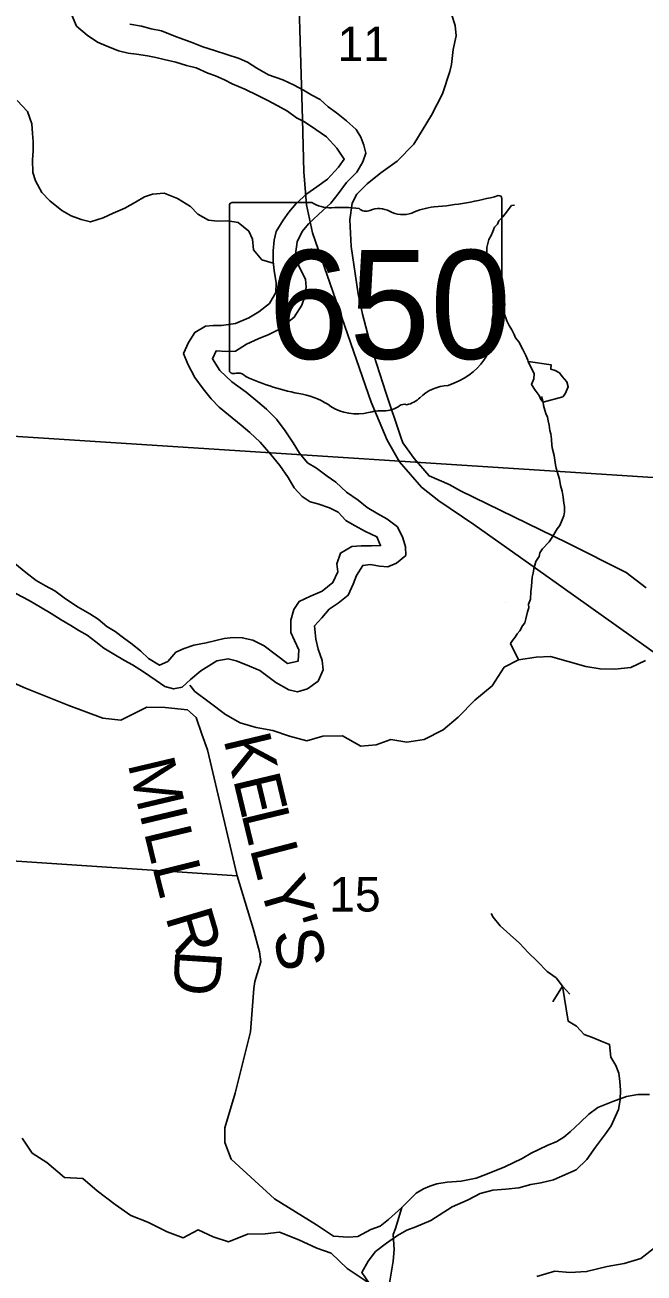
# Model space of a CAD drawing. Extents: x 0 to 44, y -23.8 to 22.
# Drawn here: x 4.521 to 5.27, y 16.572 to 18.084 of the extents above; entities that cross this region are included whole.
import ezdxf

# ---------------------------------------------------------------- set-up
doc = ezdxf.new("R2010")
doc.units = 0
for name, color, linetype in [('GM_X_County_Road', 7, 'Continuous'), ('GM_X_County_Road_Text', 7, 'Continuous'), ('GM_X_Minor_Lake', 7, 'Continuous'), ('GM_X_Minor_River', 7, 'Continuous'), ('GM_X_Rail_Line', 7, 'Continuous'), ('GM_X_Section', 7, 'Continuous'), ('GM_X_Section_Text', 7, 'Continuous'), ('GM_X_State_Location', 7, 'Continuous'), ('GM_X_State_Route', 7, 'Continuous'), ('GM_X_State_Shield', 7, 'Continuous'), ('GM_X_Township_Road', 7, 'Continuous')]:
    doc.layers.add(name, color=color, linetype=linetype)

msp = doc.modelspace()

# ---------------------------------------------------------------- linework, layer by layer
at = {"layer": 'GM_X_County_Road'}
for points in [[(4.475, 17.3011), (4.5217, 17.2806), (4.574, 17.2594), (4.6153, 17.2442), (4.6369, 17.2419), (4.6687, 17.2575), (4.6907, 17.2571), (4.7179, 17.2541), (4.7281, 17.2449), (4.735, 17.2246), (4.7419, 17.2057), (4.7758, 17.0618)], [(4.7758, 17.0618), (4.7778, 17.0531), (4.7972, 16.9895), (4.805, 16.9609), (4.8064, 16.949), (4.7991, 16.9251), (4.798, 16.9168), (4.7939, 16.8642), (4.7754, 16.7897), (4.763, 16.7478), (4.7631, 16.7299), (4.7708, 16.7097), (4.8229, 16.6618), (4.874, 16.6303), (4.8944, 16.6164), (4.9121, 16.6152), (4.924, 16.6162), (4.9398, 16.6247), (4.9511, 16.6288), (4.9611, 16.6368), (4.9774, 16.6512), (4.9947, 16.6687), (5.0036, 16.6741), (5.011, 16.6773), (5.0195, 16.6798), (5.0322, 16.6822), (5.0489, 16.6833), (5.0674, 16.687), (5.079, 16.6911), (5.1019, 16.7007), (5.1229, 16.7107), (5.1339, 16.7172), (5.1532, 16.7263), (5.1648, 16.7314), (5.1732, 16.7365), (5.1812, 16.7428), (5.1933, 16.7543), (5.2036, 16.7644), (5.2147, 16.7726), (5.2326, 16.7799), (5.2494, 16.7856), (5.2631, 16.7882), (5.2772, 16.7884)]]:
    msp.add_lwpolyline(points, dxfattribs=at)
at = {"layer": 'GM_X_Minor_Lake'}
for points in [[(5.1303, 17.6764), (5.1374, 17.6615), (5.137, 17.6554), (5.1343, 17.6482), (5.1388, 17.6417), (5.1436, 17.6352), (5.1455, 17.6303), (5.1482, 17.627)], [(5.1482, 17.627), (5.172, 17.6335), (5.1751, 17.6369), (5.1786, 17.6456), (5.1771, 17.6517), (5.1714, 17.6582), (5.1681, 17.6624), (5.1628, 17.6655), (5.1575, 17.667), (5.1575, 17.6678), (5.1579, 17.6723), (5.1303, 17.6764)]]:
    msp.add_lwpolyline(points, dxfattribs=at)
at = {"layer": 'GM_X_Minor_River'}
for points in [[(4.5777, 18.0959), (4.5834, 18.0826), (4.5963, 18.0716), (4.6089, 18.0632), (4.6191, 18.0586)], [(4.8717, 17.3562), (4.8805, 17.3657), (4.8892, 17.376), (4.9002, 17.3836), (4.9124, 17.3931), (4.9185, 17.4064), (4.9223, 17.417), (4.9299, 17.4292), (4.9394, 17.4303), (4.9501, 17.4284), (4.9603, 17.4276), (4.9706, 17.4318), (4.982, 17.4413), (4.9816, 17.4519), (4.9786, 17.4626), (4.9718, 17.4759), (4.9592, 17.4858), (4.9482, 17.4915), (4.9353, 17.4995), (4.9243, 17.5082), (4.9102, 17.5181), (4.8973, 17.5299), (4.887, 17.5375), (4.8741, 17.547), (4.8631, 17.5535), (4.8532, 17.5653), (4.8456, 17.5779), (4.8361, 17.5923), (4.8255, 17.6064), (4.8134, 17.6186), (4.8031, 17.6273), (4.7887, 17.6391), (4.7716, 17.6517), (4.7571, 17.6654), (4.748, 17.6794), (4.7526, 17.6893), (4.7648, 17.6885), (4.7758, 17.6889), (4.7891, 17.6973), (4.8035, 17.7037), (4.8161, 17.709), (4.8282, 17.7151), (4.8469, 17.7299), (4.856, 17.7443), (4.8598, 17.755), (4.8613, 17.7664), (4.8606, 17.7759), (4.853, 17.7911), (4.8485, 17.8063), (4.8507, 17.8211), (4.8565, 17.8337), (4.8644, 17.8432), (4.8762, 17.8542), (4.8911, 17.8682), (4.9002, 17.8792), (4.9101, 17.8933), (4.9226, 17.9058), (4.9299, 17.918), (4.9337, 17.9286), (4.9314, 17.9385), (4.9276, 17.948), (4.9219, 17.9575), (4.9101, 17.9678), (4.898, 17.9777), (4.8881, 17.9849), (4.8782, 17.9937), (4.8683, 17.999), (4.8581, 18.0051), (4.8467, 18.0112), (4.833, 18.0173), (4.8159, 18.0237), (4.8015, 18.0317), (4.7905, 18.039), (4.7802, 18.0435), (4.7654, 18.0481), (4.7506, 18.0531), (4.7365, 18.0576), (4.7224, 18.063), (4.7122, 18.0668), (4.7012, 18.071), (4.6863, 18.0767), (4.6738, 18.0794), (4.662, 18.0824), (4.648, 18.0851)], [(4.6191, 18.0586), (4.6343, 18.0525), (4.6461, 18.0499), (4.656, 18.0487), (4.6693, 18.0464), (4.6795, 18.0445), (4.6894, 18.0422), (4.7035, 18.0388), (4.7164, 18.035), (4.7282, 18.0319), (4.7422, 18.0255), (4.7517, 18.0224), (4.7624, 18.0175), (4.7719, 18.0125), (4.7871, 18.006), (4.803, 17.9984), (4.8144, 17.9927), (4.827, 17.9858), (4.8387, 17.9794), (4.8498, 17.9714), (4.8593, 17.9668), (4.8733, 17.9573), (4.8862, 17.9485), (4.8984, 17.9348), (4.9075, 17.9215), (4.9006, 17.9117), (4.8873, 17.8972), (4.8744, 17.8877), (4.8622, 17.8794), (4.8493, 17.8676), (4.8406, 17.857), (4.8337, 17.8475), (4.825, 17.8338), (4.8227, 17.8232), (4.8215, 17.8102), (4.8215, 17.7973), (4.8226, 17.7863), (4.8249, 17.7715), (4.8245, 17.7597), (4.8169, 17.7464), (4.804, 17.7365), (4.7922, 17.7293), (4.7759, 17.7221), (4.7591, 17.7198), (4.7489, 17.7198), (4.7394, 17.7191), (4.7268, 17.7115), (4.7188, 17.6993), (4.7131, 17.686), (4.718, 17.6731), (4.7268, 17.6568), (4.7367, 17.6431), (4.7465, 17.6309), (4.756, 17.621), (4.7674, 17.6115), (4.7826, 17.5993), (4.7932, 17.5902), (4.8058, 17.5784), (4.8187, 17.5636), (4.8297, 17.5502), (4.8396, 17.5358), (4.8468, 17.5232), (4.8567, 17.5126), (4.8662, 17.5061), (4.8757, 17.5038), (4.8897, 17.4989), (4.9, 17.4936), (4.9095, 17.4837), (4.9201, 17.4776), (4.9334, 17.4703), (4.9471, 17.4639), (4.9516, 17.4532), (4.9406, 17.4528), (4.9281, 17.4529), (4.9167, 17.4521), (4.903, 17.4441), (4.8984, 17.4312), (4.8999, 17.4213), (4.8938, 17.4084), (4.8809, 17.3982), (4.8668, 17.3921), (4.8528, 17.3856), (4.8463, 17.3758), (4.8429, 17.3628), (4.8429, 17.348), (4.8474, 17.3381), (4.8527, 17.3271), (4.8516, 17.313), (4.8387, 17.3104), (4.8254, 17.3203), (4.8106, 17.3317), (4.7969, 17.3386), (4.784, 17.3416), (4.7729, 17.342), (4.7623, 17.3405), (4.752, 17.3382), (4.7402, 17.3356), (4.7254, 17.3325), (4.7136, 17.3284), (4.7037, 17.3242), (4.6939, 17.3128)], [(4.5114, 17.9923), (4.5239, 17.9792), (4.5295, 17.964), (4.5302, 17.9526), (4.5309, 17.9427), (4.5308, 17.9313), (4.5303, 17.9207), (4.5306, 17.9051), (4.5336, 17.8952), (4.5415, 17.8811), (4.5513, 17.8711), (4.5657, 17.8592), (4.577, 17.8527), (4.5892, 17.8484), (4.6002, 17.8453), (4.6158, 17.8505), (4.6276, 17.8558), (4.6417, 17.8621), (4.6547, 17.8692), (4.6658, 17.8756), (4.6753, 17.879), (4.6897, 17.88), (4.7057, 17.8738), (4.7212, 17.8642), (4.7303, 17.8546), (4.7431, 17.8473), (4.7541, 17.8461), (4.7667, 17.8468), (4.7792, 17.8448), (4.7921, 17.8341), (4.7966, 17.8245), (4.7976, 17.8116), (4.8078, 17.7994), (4.8215, 17.7955)], [(5.1303, 17.6764), (5.1298, 17.6777), (5.1272, 17.6835), (5.1239, 17.6907), (5.1187, 17.6999), (5.115, 17.7049), (5.1131, 17.7091), (5.1105, 17.7148), (5.1072, 17.7198), (5.1042, 17.7255), (5.1013, 17.7347), (5.0979, 17.7408), (5.0957, 17.7473), (5.0935, 17.7534), (5.0913, 17.7584), (5.0895, 17.7664), (5.0877, 17.7732), (5.0862, 17.7771), (5.0848, 17.7839), (5.0826, 17.7915), (5.0811, 17.7988), (5.0801, 17.8053), (5.0802, 17.8144), (5.0826, 17.8242), (5.0853, 17.8287), (5.0876, 17.8337), (5.0896, 17.839), (5.093, 17.8427), (5.0946, 17.8465), (5.0996, 17.8514), (5.1023, 17.8551), (5.11, 17.8653), (5.1138, 17.8656)], [(5.118, 17.3155), (5.1088, 17.3345), (5.1111, 17.3383), (5.1146, 17.3424), (5.1169, 17.3462), (5.12, 17.35), (5.1234, 17.356), (5.1261, 17.3598), (5.1273, 17.3643), (5.1293, 17.373), (5.1309, 17.3779), (5.1306, 17.3821), (5.1329, 17.3882), (5.1334, 17.3973), (5.1342, 17.4041), (5.1351, 17.4151), (5.1363, 17.42), (5.1371, 17.425), (5.1395, 17.4341), (5.1434, 17.4401), (5.1442, 17.4446), (5.1477, 17.4492), (5.1557, 17.4578), (5.1581, 17.4616), (5.1611, 17.4668), (5.1654, 17.4736), (5.1685, 17.4774), (5.1712, 17.4846), (5.1732, 17.4891), (5.174, 17.494), (5.1741, 17.5005), (5.1733, 17.5047), (5.1727, 17.5119), (5.1712, 17.5191), (5.1694, 17.526), (5.168, 17.5336), (5.1654, 17.5428), (5.164, 17.547), (5.1633, 17.5512), (5.1615, 17.5622), (5.1597, 17.5702), (5.159, 17.5744), (5.1583, 17.582), (5.1576, 17.5888), (5.1565, 17.5927), (5.1555, 17.5991), (5.1544, 17.6045), (5.1537, 17.609), (5.1515, 17.6132), (5.1504, 17.6174), (5.1489, 17.6231), (5.1482, 17.627), (5.1471, 17.6312), (5.1464, 17.634)], [(4.6939, 17.3128), (4.684, 17.3082), (4.6707, 17.3166), (4.6612, 17.3254), (4.6509, 17.3337), (4.6403, 17.3414), (4.63, 17.3493), (4.6202, 17.3554), (4.6095, 17.3642), (4.5996, 17.3707), (4.5852, 17.3786), (4.57, 17.3889), (4.5571, 17.3984), (4.5457, 17.4045), (4.5347, 17.411), (4.5221, 17.4205), (4.5088, 17.4315)], [(4.5099, 17.3953), (4.5259, 17.3866), (4.5399, 17.3786), (4.5528, 17.371), (4.565, 17.3633), (4.5764, 17.3565), (4.5863, 17.3504), (4.5962, 17.3447), (4.6068, 17.3367), (4.6163, 17.3291), (4.6284, 17.3215), (4.6414, 17.3142), (4.6512, 17.3089), (4.6645, 17.3002), (4.6797, 17.2899), (4.6904, 17.2827), (4.701, 17.2796), (4.7113, 17.2819), (4.7215, 17.291), (4.7341, 17.3016), (4.7531, 17.3138), (4.7668, 17.316), (4.7767, 17.3137), (4.7881, 17.3092), (4.8052, 17.3019), (4.8245, 17.2875), (4.8405, 17.2783), (4.8508, 17.2761), (4.8629, 17.2795), (4.8758, 17.289), (4.8819, 17.3026), (4.8808, 17.314), (4.8759, 17.3277), (4.8732, 17.3399), (4.8717, 17.3562)], [(5.2723, 17.3141), (5.2544, 17.3055), (5.235, 17.3037), (5.2172, 17.3038), (5.1998, 17.3069), (5.1786, 17.3127), (5.1574, 17.3189), (5.14, 17.3182), (5.1183, 17.3149), (5.1012, 17.3059), (5.0866, 17.2832), (5.0657, 17.2658), (5.0454, 17.2454), (5.0271, 17.23), (5.0043, 17.2183), (4.9834, 17.215), (4.9641, 17.2181), (4.9462, 17.2118), (4.9276, 17.2104), (4.9053, 17.2226), (4.8815, 17.2224), (4.8621, 17.2168), (4.8413, 17.2222), (4.8212, 17.2291), (4.8008, 17.2327), (4.7814, 17.2385), (4.7637, 17.2484), (4.7441, 17.2637), (4.7267, 17.2763), (4.7207, 17.2842)], [(5.1807, 16.9096), (5.1717, 16.9195), (5.1642, 16.9294), (5.1532, 16.9371), (5.1416, 16.9493), (5.1303, 16.9604), (5.1198, 16.9715), (5.1085, 16.9818), (5.0964, 16.9925), (5.0878, 17.0032), (5.0855, 17.0074)], [(5.2303, 16.8333), (5.2287, 16.8489), (5.2185, 16.8528), (5.208, 16.8571), (5.1978, 16.8609), (5.1888, 16.8708), (5.1786, 16.877), (5.1717, 16.9195), (5.1606, 16.9014), (5.1606, 16.9006)], [(4.9377, 16.5598), (4.9289, 16.5726), (4.9365, 16.5862), (4.9452, 16.598), (4.9588, 16.6079), (4.972, 16.6173), (4.9834, 16.6238), (4.9943, 16.628), (5.0125, 16.6356), (5.0382, 16.6523), (5.0575, 16.6606), (5.0722, 16.6682), (5.0873, 16.6724), (5.1032, 16.6735), (5.1187, 16.6751), (5.1335, 16.6792), (5.1456, 16.6811), (5.1607, 16.6849), (5.1716, 16.6895), (5.1883, 16.6971), (5.2011, 16.7096), (5.2117, 16.7244), (5.2238, 16.7407), (5.2306, 16.7502), (5.2397, 16.7699), (5.2416, 16.7817), (5.242, 16.7934), (5.2412, 16.8041), (5.2401, 16.8139), (5.2363, 16.8234), (5.2303, 16.8333)], [(4.5176, 16.7355), (4.5297, 16.7172), (4.5474, 16.7058), (4.569, 16.6875), (4.5909, 16.6864), (4.6083, 16.6715), (4.6302, 16.6548), (4.6491, 16.6418), (4.6699, 16.6334), (4.693, 16.622), (4.7126, 16.6144), (4.7305, 16.6242), (4.749, 16.6159), (4.7675, 16.6098), (4.7902, 16.6189), (4.8118, 16.6196), (4.8292, 16.6215), (4.8527, 16.612), (4.8742, 16.6021), (4.8916, 16.596), (4.9109, 16.5773), (4.9377, 16.5598)], [(5.1407, 16.5676), (5.1623, 16.574), (5.1808, 16.5725), (5.2009, 16.5736), (5.2259, 16.5797), (5.2463, 16.5834), (5.2664, 16.5895), (5.2869, 16.6051), (5.3077, 16.6279), (5.3286, 16.6381), (5.3505, 16.6297), (5.369, 16.6164), (5.3898, 16.605), (5.4046, 16.5848), (5.4231, 16.5646)]]:
    msp.add_lwpolyline(points, dxfattribs=at)
at = {"layer": 'GM_X_Rail_Line'}
msp.add_lwpolyline([(5.3735, 17.2591), (5.121, 17.4386), (5.0645, 17.4786), (5.0219, 17.5076), (5.0011, 17.5239), (4.9745, 17.5545), (4.9593, 17.581), (4.94, 17.6269), (4.8692, 17.8321), (4.8619, 17.8659), (4.8587, 17.9061), (4.8571, 17.9697), (4.8434, 18.4308), (4.8378, 18.5668), (4.8338, 18.5966), (4.8281, 18.6424), (4.8129, 18.7245), (4.7815, 18.8919)], dxfattribs=at)
at = {"layer": 'GM_X_Section'}
for points in [[(4.4853, 18.6191), (5.5009, 18.5537), (5.4377, 17.5257), (4.437, 17.5902)], [(4.437, 17.5902), (5.4377, 17.5257), (5.3718, 16.5024), (4.3733, 16.5584)]]:
    msp.add_lwpolyline(points, close=True, dxfattribs=at)
at = {"layer": 'GM_X_State_Route'}
msp.add_lwpolyline([(5.2731, 17.402), (5.2489, 17.4205), (5.1774, 17.4566), (5.0482, 17.5195), (5.0345, 17.5272), (5.0102, 17.5378), (4.992, 17.5589), (4.9786, 17.5779), (4.9761, 17.5844), (4.9577, 17.6385), (4.9396, 17.6953), (4.9297, 17.7336), (4.9245, 17.7581), (4.9159, 17.8157), (4.9142, 17.848), (4.9172, 17.8682), (4.9229, 17.8791), (4.9353, 17.8915), (4.9518, 17.9048), (4.9714, 17.919), (4.9916, 17.9396), (5.0131, 17.9748), (5.0264, 18.0005), (5.0355, 18.0275), (5.0374, 18.0362), (5.0392, 18.0541), (5.0429, 18.0706), (5.0419, 18.0834), (5.0328, 18.1109)], dxfattribs=at)
at = {"layer": 'GM_X_State_Shield'}
for p, q in [((5.0982, 17.7691), (5.0982, 17.8738)), ((4.7686, 17.8654), (4.7686, 17.6653)), ((4.8684, 17.8689), (4.7718, 17.8689)), ((5.0981, 17.7692), (5.0982, 17.7691))]:
    msp.add_line(p, q, dxfattribs=at)
for centre, major_axis, start_param, end_param in [((4.9808, 18.1417), (0.3495, 0), 4.814394, 5.042369), ((5.0945, 17.8743), (0.00367, 0), 6.141152, 7.989035), ((4.7724, 17.8659), (0.00382, 0), 1.712693, 3.28349), ((4.8913, 17.8921), (0.037, 0), 4.042523, 4.731795), ((4.9036, 17.7565), (0.133, 0), 1.404758, 1.657858), ((4.9338, 17.8669), (0.0107, 0), 3.836095, 5.185415), ((4.9495, 17.8438), (0.0222, 0), 0.950623, 2.079405), ((4.9782, 17.8755), (0.0267, 0), 4.081561, 5.145723), ((5.0253, 17.8077), (0.0703, 0), 1.699011, 2.107814), ((5.0943, 17.7687), (0.00393, 0), 5.05454, 6.418171), ((5.0973, 17.7615), (0.00568, 0), 1.883978, 3.671073), ((5.0612, 17.7482), (0.0341, 0), 5.934695, 6.695948), ((5.1113, 17.7253), (0.0248, 0), 2.387724, 3.262537), ((5.0003, 17.712), (0.0874, 0), 5.101752, 6.440018), ((4.7724, 17.6649), (0.00385, 0), 3.00124, 4.508301), ((4.773, 17.6853), (0.0294, 0), 4.665946, 4.897461), ((4.779, 17.6538), (0.0106, 0), 0.519207, 1.627899), ((4.9128, 17.8336), (0.2524, 0), 4.195997, 4.488961), ((5.0372, 17.6091), (0.0479, 0), 1.647645, 2.488434), ((4.8376, 17.5754), (0.079, 0), 0.823519, 1.323587), ((4.9765, 17.6459), (0.0282, 0), 4.937069, 5.64225), ((4.923, 17.6528), (0.0501, 0), 4.026481, 4.996735), ((4.9519, 17.5836), (0.0412, 0), 1.495662, 1.94098), ((4.9556, 17.6378), (0.0267, 0), 4.691044, 5.507374), ((4.9798, 17.6184), (0.00752, 0), 1.147584, 2.315152)]:
    msp.add_ellipse(centre, major_axis=major_axis, ratio=0.8, start_param=start_param, end_param=end_param, dxfattribs=at)
at = {"layer": 'GM_X_Township_Road'}
msp.add_line((4.4054, 17.078), (4.7778, 17.0531), dxfattribs=at)
msp.add_lwpolyline([(4.9774, 16.6512), (4.9696, 16.6259), (4.9667, 16.6184), (4.9678, 16.6004), (4.9667, 16.5864), (4.9618, 16.5574), (4.9657, 16.5347), (4.9672, 16.5303), (4.9718, 16.5246), (4.9764, 16.5218), (4.9902, 16.52), (5.0035, 16.52), (5.006, 16.5184), (5.0087, 16.5161), (5.018, 16.5035), (5.0251, 16.5006), (5.0456, 16.5019), (5.0587, 16.4997), (5.0644, 16.4955), (5.0744, 16.4847), (5.1523, 16.334), (5.1557, 16.3183)], dxfattribs=at)

# ---------------------------------------------------------------- texts
at = {"layer": 'GM_X_County_Road_Text'}
for s, rotation, p in [('K', 283.4743, (4.7611, 17.2187)), ('M', 283.3313, (4.6451, 17.1893)), ('E', 283.4692, (4.7727, 17.1701)), ('I', 283.3898, (4.6594, 17.1292)), ('L', 283.583, (4.7827, 17.1286)), ('L', 283.5846, (4.6648, 17.1063)), ('L', 284.6517, (4.7929, 17.0862)), ('L', 284.1107, (4.6749, 17.0645)), ('Y', 286.3844, (4.8042, 17.0432)), ('R', 286.544, (4.6906, 17.0039)), ("'", 286.2757, (4.8183, 16.9953)), ('S', 280.6232, (4.8214, 16.9847)), ('D', 266.2854, (4.7033, 16.9644))]:
    msp.add_text(s, height=0.0568, rotation=rotation, dxfattribs=at).set_placement(p)
at = {"layer": 'GM_X_Section_Text'}
for s, p in [('11', (4.8993, 18.0402)), ('15', (4.8893, 17.0099))]:
    msp.add_text(s, height=0.04186, rotation=0, dxfattribs=at).set_placement(p)
at = {"layer": 'GM_X_State_Location'}
for s in ['s', 'r']:
    msp.add_text(s, height=0.000189, dxfattribs=at).set_placement((5.1695, 17.3975))
msp.add_text('650', height=0.000189, rotation=0, dxfattribs=at).set_placement((5.1027, 17.3838))
at = {"layer": 'GM_X_State_Shield'}
msp.add_text('650', height=0.13184, dxfattribs=at).set_placement((4.8155, 17.6794))

doc.saveas('drawing.dxf')
